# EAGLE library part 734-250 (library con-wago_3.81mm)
Serie 734, Stiftleiste (für Leiterplatten) Einlötstift gerade 1 x 1 mm / Series 734, Male header (for PCBs) Straight solder pin 1 x 1 mm Polzahl / Pole No.: 20 Rastermaß / Pitch: 3.81 mm Bemessungsspannung / Rated Voltage: 160 V Nennstrom / Nominal Current: 10 A Lötstiftlänge: / Solder Pin Length: 4.5 mm Farbe / Color: orange / orange Stand: 01.01.2012. Die jeweils aktuellen Daten zu diesem Artikel finden Sie in unserem Produktkatalog, den Sie unter www.wago.com einsehen können. As of: 01/01/2012. Please find the newest data for this article in our product catalogue, which can be viewed under www.wago.com.
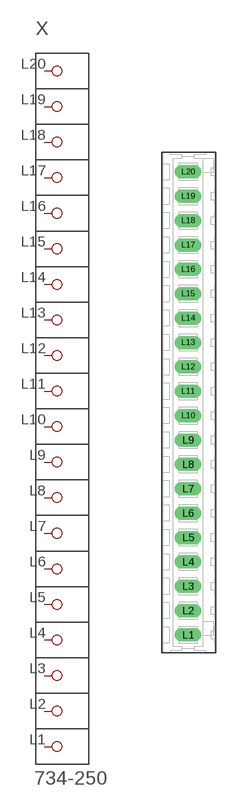
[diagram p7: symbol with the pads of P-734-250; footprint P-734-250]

Designator prefix X

## 734-250  [P-734-250]
L1  P1
L2  P2
L3  P3
L4  P4
L5  P5
L6  P6
L7  P7
L8  P8
L9  P9
L10  P10
L11  P11
L12  P12
L13  P13
L14  P14
L15  P15
L16  P16
L17  P17
L18  P18
L19  P19
L20  P20

## Footprint P-734-250 (pad centres in mm)
drill 1.4 long: L1 -0.1,-36.345; L2 -0.1,-32.535; L3 -0.1,-28.725; L4 -0.1,-24.915; L5 -0.1,-21.105; L6 -0.1,-17.295; L7 -0.1,-13.485; L8 -0.1,-9.675; L9 -0.1,-5.865; L10 -0.1,-2.055; L11 -0.1,1.755; L12 -0.1,5.565; L13 -0.1,9.375; L14 -0.1,13.185; L15 -0.1,16.995; L16 -0.1,20.805; L17 -0.1,24.615; L18 -0.1,28.425; L19 -0.1,32.235; L20 -0.1,36.045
